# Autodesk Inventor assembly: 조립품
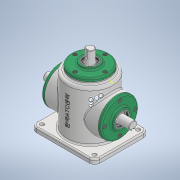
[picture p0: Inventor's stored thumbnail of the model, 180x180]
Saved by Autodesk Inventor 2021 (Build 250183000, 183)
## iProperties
Created: 2021-02
Part Number: 조립품
Document SubType Name: Assembly
Designer: mdu2-97
Author: mdu2-97
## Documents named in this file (16)
- C:\Users\mdu2-97\Desktop\710214V1002\조립품.iam
- C:\Users\mdu2-97\Desktop\710214V1002\본체.ipt
- C:\Users\mdu2-97\Desktop\710214V1002\커버.ipt
- C:\Users\mdu2-97\Desktop\710214V1002\베어링 6203.ipt
- C:\Users\mdu2-97\Desktop\710214V1002\오일 실.ipt
- 오일 실.ipt
- C:\Users\mdu2-97\Desktop\710214V1002\메인 축.ipt
- 메인 축.ipt
- C:\Users\mdu2-97\Desktop\710214V1002\키 5x5.ipt
- C:\Users\mdu2-97\Desktop\710214V1002\메인 베벨기어.ipt
- C:\Users\mdu2-97\Desktop\710214V1002\서브 축.ipt
- 서브 축.ipt
- C:\Users\mdu2-97\Desktop\710214V1002\키 4x4.ipt
- C:\Users\mdu2-97\Desktop\710214V1002\서브 베벨기어.ipt
- C:\Users\mdu2-97\Desktop\710214V1002\볼트 M4.ipt
- 볼트 M4.ipt
